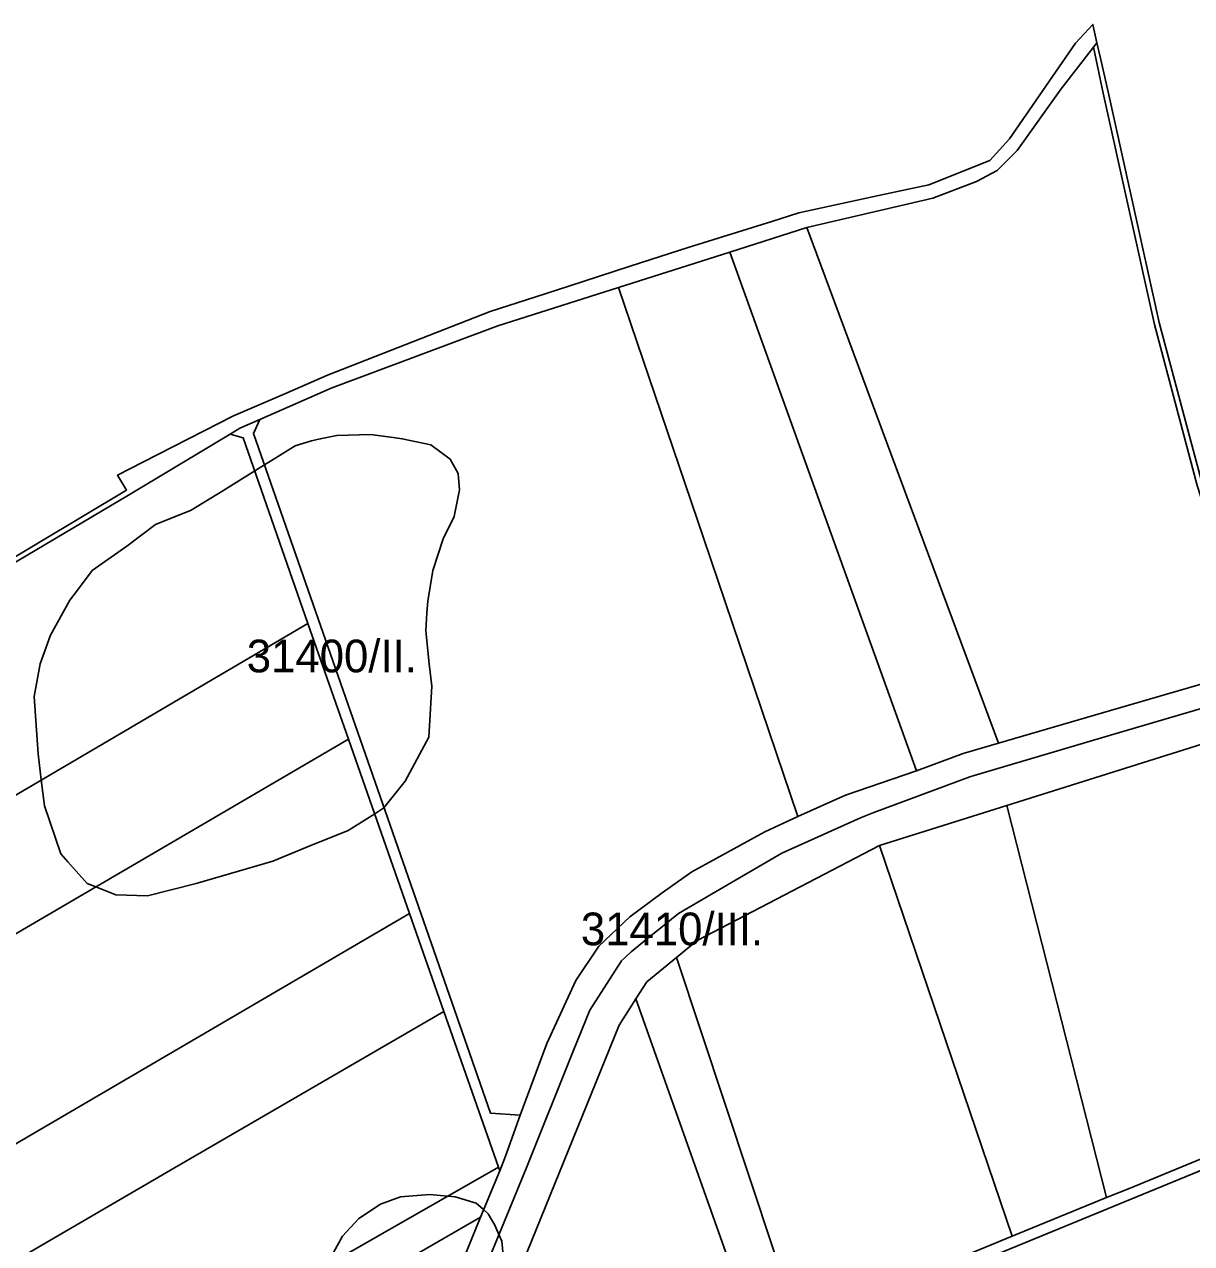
# Model space of a CAD drawing. Extents: x -522079 to -518792, y -1142400 to -1139961.
# Drawn here: x -520538 to -520002, y -1140521 to -1139961 of the extents above; entities that cross this region are included whole.
import ezdxf

# ---------------------------------------------------------------- set-up
doc = ezdxf.new("R2010")
doc.units = 0
for name, color, linetype in [('Hranice parcel', 7, 'Continuous'), ('Parcelní čísla', 7, 'Continuous'), ('Poz předměty', 7, 'Continuous'), ('Značky bodu BP', 7, 'Continuous')]:
    doc.layers.add(name, color=color, linetype=linetype)

msp = doc.modelspace()

# ---------------------------------------------------------------- linework, layer by layer
at = {"layer": 'Hranice parcel'}
for points in [[(-520611.62, -1140247.2), (-520491.09, -1140175.17), (-520495.34, -1140168.3), (-520483.64, -1140162.33), (-520442, -1140141.08), (-520418.53, -1140130.92), (-520398.93, -1140122.43), (-520359.48, -1140107), (-520324.32, -1140093.25), (-520303.34, -1140086.47), (-520288.09, -1140081.53), (-520260.01, -1140072.45), (-520246.26, -1140068.01), (-520233.47, -1140063.87), (-520226.58, -1140061.71), (-520194.98, -1140051.81), (-520182.69, -1140047.96), (-520145.26, -1140039.86), (-520123.02, -1140035.05), (-520094.95, -1140023.82), (-520085.97, -1140013.91), (-520055.62, -1139970.09), (-520047.76, -1139961.42), (-520045.81, -1139969.91), (-520047.4, -1139971.94), (-520062.19, -1139990.92), (-520082.48, -1140019.36), (-520091.68, -1140028.41), (-520101.17, -1140033.45), (-520121.19, -1140041.17), (-520178.95, -1140054.65), (-520214.32, -1140065.91), (-520265.37, -1140082.17), (-520320.72, -1140099.79), (-520397.23, -1140128.42), (-520429.91, -1140142.73), (-520439.13, -1140146.77), (-520443.64, -1140149.48), (-520489.41, -1140176.97), (-520610.57, -1140248.68)], [(-520342.62, -1140543.01), (-520328.73, -1140508.82), (-520319.85, -1140487.51), (-520317.29, -1140480.75), (-520310.52, -1140461.93), (-520298.27, -1140429.16), (-520285.01, -1140400.23), (-520274.33, -1140384.38), (-520260.24, -1140370.94), (-520245.33, -1140359.99), (-520231.71, -1140350.36), (-520198.24, -1140332), (-520183.06, -1140324.86), (-520161.16, -1140315.09), (-520128.63, -1140303.97), (-520107.24, -1140295.95), (-520091.03, -1140291.29), (-520039.59, -1140276.29), (-519972.75, -1140256.9)], [(-519993.22, -1140274.03), (-520037.05, -1140286.83), (-520102.1, -1140306.15), (-520104.17, -1140306.68), (-520148.17, -1140323.1), (-520154.29, -1140325.48), (-520190.37, -1140341.83), (-520222.7, -1140360.61), (-520237.84, -1140369.42), (-520246.72, -1140376.59), (-520251.21, -1140380.2), (-520259.52, -1140387.05), (-520263.92, -1140391.15), (-520278.46, -1140413.78), (-520286.11, -1140432.61), (-520307.77, -1140486.46), (-520327.66, -1140534.75)], [(-519947.24, -1140466.47), (-520104.66, -1140531.14), (-520155.91, -1140552.2), (-520167.57, -1140556.99), (-520262.2, -1140595.87), (-520287.56, -1140604.5), (-520318.61, -1140618.22), (-520330.21, -1140624.54), (-520334.77, -1140627.95), (-520334.5, -1140634.63), (-520342.44, -1140624.55), (-520317.54, -1140611.38), (-520303.27, -1140605.8), (-520289.45, -1140599.87), (-520277.29, -1140595.78), (-520263.96, -1140591.19), (-520201.76, -1140565.63), (-520182.86, -1140557.87), (-520106.55, -1140526.52), (-520084.71, -1140517.54), (-520041.44, -1140499.76), (-520031.39, -1140495.83), (-519949.02, -1140461.79)]]:
    msp.add_lwpolyline(points, dxfattribs=at)
msp.add_lwpolyline([(-520044.21, -1139976.9), (-520040.68, -1139992.3), (-520017.23, -1140098.3), (-519997.42, -1140172.65), (-519970.54, -1140256.24), (-519972.75, -1140256.9), (-519999.86, -1140173.01), (-520019.48, -1140099.15), (-520042.94, -1139993.02), (-520047.4, -1139971.94), (-520045.81, -1139969.91)], close=True, dxfattribs=at)
at = {"layer": 'Parcelní čísla'}
for points in [[(-520178.95, -1140054.65), (-520121.19, -1140041.17), (-520101.17, -1140033.45), (-520091.68, -1140028.41), (-520082.48, -1140019.36), (-520062.19, -1139990.92), (-520047.4, -1139971.94), (-520042.94, -1139993.02), (-520019.48, -1140099.15), (-519999.86, -1140173.01), (-519972.75, -1140256.9), (-520039.59, -1140276.29), (-520091.03, -1140291.29)], [(-520091.03, -1140291.29), (-520107.24, -1140295.95), (-520128.63, -1140303.97), (-520170.5, -1140187.64), (-520214.32, -1140065.91), (-520178.95, -1140054.65)], [(-520265.37, -1140082.17), (-520214.32, -1140065.91), (-520170.5, -1140187.64), (-520128.63, -1140303.97), (-520161.16, -1140315.09), (-520183.06, -1140324.86), (-520226.42, -1140197.01)], [(-520320.72, -1140099.79), (-520265.37, -1140082.17), (-520226.42, -1140197.01), (-520183.06, -1140324.86), (-520198.24, -1140332), (-520231.71, -1140350.36), (-520245.33, -1140359.99), (-520260.24, -1140370.94), (-520274.33, -1140384.38), (-520285.01, -1140400.23), (-520298.27, -1140429.16), (-520310.52, -1140461.93), (-520324.15, -1140461.03), (-520370.19, -1140328.97), (-520432.89, -1140149.1), (-520429.91, -1140142.73), (-520397.23, -1140128.42)], [(-520432.89, -1140149.1), (-520370.19, -1140328.97), (-520324.15, -1140461.03), (-520310.52, -1140461.93), (-520317.29, -1140480.75), (-520319.85, -1140487.51), (-520320.44, -1140485.82), (-520345.47, -1140414.38), (-520361.23, -1140369.4), (-520389.24, -1140289.48), (-520407.86, -1140236.34), (-520437.53, -1140151.12), (-520443.64, -1140149.48), (-520439.13, -1140146.77), (-520429.91, -1140142.73)], [(-520697.54, -1140405.82), (-520704.93, -1140387.92), (-520719.64, -1140344.89), (-520729.96, -1140323.84), (-520727.12, -1140316.09), (-520610.57, -1140248.68), (-520489.41, -1140176.97), (-520443.64, -1140149.48), (-520437.53, -1140151.12), (-520407.86, -1140236.34), (-520563.45, -1140327.62)], [(-520407.86, -1140236.34), (-520389.24, -1140289.48), (-520535.21, -1140374.77), (-520673.87, -1140455.8), (-520683.48, -1140439.85), (-520697.54, -1140405.82), (-520563.45, -1140327.62)], [(-520087.13, -1140319.85), (-519973.33, -1140284.13), (-519917.2, -1140450.72), (-519949.02, -1140461.79), (-520031.39, -1140495.83), (-520041.44, -1140499.76)], [(-520592.52, -1140504.62), (-520608.7, -1140486.32), (-520623.97, -1140478.75), (-520659.41, -1140472.47), (-520666.98, -1140467.24), (-520673.87, -1140455.8), (-520535.21, -1140374.77), (-520389.24, -1140289.48), (-520361.23, -1140369.4)], [(-520041.44, -1140499.76), (-520084.71, -1140517.54), (-520145.65, -1140338.22), (-520087.13, -1140319.85)], [(-520238.71, -1140389.58), (-520229.31, -1140381.82), (-520145.65, -1140338.22), (-520084.71, -1140517.54), (-520106.55, -1140526.52), (-520182.86, -1140557.87)], [(-520361.23, -1140369.4), (-520345.47, -1140414.38), (-520469.06, -1140486.19), (-520562.49, -1140540.48), (-520587.65, -1140510.13), (-520592.52, -1140504.62)], [(-520182.86, -1140557.87), (-520201.76, -1140565.63), (-520257.35, -1140408.66), (-520252.32, -1140400.85), (-520238.71, -1140389.58)], [(-520201.76, -1140565.63), (-520263.96, -1140591.19), (-520277.29, -1140595.78), (-520289.45, -1140599.87), (-520311.64, -1140535.23), (-520265.09, -1140420.72), (-520257.35, -1140408.66)], [(-520345.47, -1140414.38), (-520320.44, -1140485.82), (-520431.13, -1140549.18), (-520503.8, -1140590.78), (-520557.7, -1140546.26), (-520562.49, -1140540.48), (-520469.06, -1140486.19)], [(-519886.24, -1140527.38), (-520082.56, -1140649.64), (-520126.03, -1140587.59), (-520155.91, -1140552.2), (-520104.66, -1140531.14), (-519947.24, -1140466.47), (-519916.36, -1140457.2), (-519904.17, -1140458.14), (-519893.54, -1140491.71)], [(-520490.09, -1140602.11), (-520503.8, -1140590.78), (-520431.13, -1140549.18), (-520320.44, -1140485.82), (-520319.85, -1140487.51), (-520328.73, -1140508.82)], [(-520459.31, -1140627.54), (-520490.09, -1140602.11), (-520328.73, -1140508.82), (-520342.62, -1140543.01), (-520348.21, -1140563.43)]]:
    msp.add_lwpolyline(points, close=True, dxfattribs=at)
at = {"layer": 'Poz předměty'}
for points in [[(-520327.66, -1140534.75), (-520307.77, -1140486.46), (-520286.11, -1140432.61), (-520278.46, -1140413.78), (-520263.92, -1140391.15), (-520259.52, -1140387.05), (-520251.21, -1140380.2), (-520246.72, -1140376.59), (-520237.84, -1140369.42), (-520222.7, -1140360.61), (-520190.37, -1140341.83), (-520154.29, -1140325.48), (-520148.17, -1140323.1), (-520104.17, -1140306.68), (-520102.1, -1140306.15), (-520037.05, -1140286.83), (-519993.22, -1140274.03)], [(-519973.33, -1140284.13), (-520087.13, -1140319.85), (-520145.65, -1140338.22), (-520229.31, -1140381.82), (-520238.71, -1140389.58), (-520252.32, -1140400.85), (-520257.35, -1140408.66), (-520265.09, -1140420.72), (-520311.64, -1140535.23)]]:
    msp.add_lwpolyline(points, dxfattribs=at)
at = {"layer": 'Značky bodu BP'}
for points in [[(-520611.62, -1140247.2), (-520491.09, -1140175.17), (-520495.34, -1140168.3), (-520483.64, -1140162.33), (-520442, -1140141.08), (-520418.53, -1140130.92), (-520398.93, -1140122.43), (-520359.48, -1140107), (-520324.32, -1140093.25), (-520303.34, -1140086.47), (-520288.09, -1140081.53), (-520260.01, -1140072.45), (-520246.26, -1140068.01), (-520233.47, -1140063.87), (-520226.58, -1140061.71), (-520194.98, -1140051.81), (-520182.69, -1140047.96), (-520145.26, -1140039.86), (-520123.02, -1140035.05), (-520094.95, -1140023.82), (-520085.97, -1140013.91), (-520055.62, -1139970.09), (-520047.76, -1139961.42), (-520045.81, -1139969.91), (-520044.21, -1139976.9), (-520040.68, -1139992.3), (-520017.23, -1140098.3), (-519997.42, -1140172.65)], [(-520398.63, -1140529.45), (-520391.98, -1140517.59), (-520384.59, -1140509.44), (-520374.62, -1140502.77), (-520365.38, -1140499.44), (-520352.08, -1140498.33), (-520343.67, -1140499.11), (-520340.26, -1140499.44), (-520330.66, -1140502.4), (-520327.28, -1140505.34), (-520325.12, -1140507.22), (-520322.16, -1140512.41), (-520320.23, -1140516.71), (-520318.84, -1140519.82), (-520318.1, -1140527.97)], [(-520318.1, -1140527.97), (-520318.84, -1140519.82), (-520320.23, -1140516.71), (-520322.16, -1140512.41), (-520325.12, -1140507.22), (-520327.28, -1140505.34), (-520330.66, -1140502.4), (-520340.26, -1140499.44), (-520343.67, -1140499.11), (-520352.08, -1140498.33), (-520365.38, -1140499.44), (-520374.62, -1140502.77), (-520384.59, -1140509.44), (-520391.98, -1140517.59), (-520398.63, -1140529.45)]]:
    msp.add_lwpolyline(points, dxfattribs=at)
for points in [[(-520533.5, -1140269.82), (-520531.63, -1140296.1), (-520530.22, -1140308.12), (-520528.82, -1140320.04), (-520521.34, -1140342.1), (-520518.05, -1140345.78), (-520509.17, -1140355.71), (-520505.24, -1140357.26), (-520496.07, -1140360.87), (-520481.57, -1140361.34), (-520459.11, -1140355.71), (-520424.02, -1140345.38), (-520408.03, -1140338.88), (-520389.4, -1140331.31), (-520377.26, -1140323.65), (-520372.99, -1140320.94), (-520363.2, -1140308.77), (-520352.44, -1140288.6), (-520351.04, -1140265.13), (-520352.18, -1140254.84), (-520353.84, -1140239.78), (-520353.27, -1140231.49), (-520352.91, -1140226.17), (-520350.57, -1140212.09), (-520345.89, -1140197.54), (-520340.74, -1140187.22), (-520338.4, -1140175.02), (-520338.87, -1140167.51), (-520342.61, -1140160.94), (-520351.5, -1140154.36), (-520364.6, -1140151.55), (-520367.65, -1140151.16), (-520370.99, -1140150.73), (-520379.11, -1140149.67), (-520394.55, -1140150.14), (-520402.25, -1140151.69), (-520406.24, -1140152.49), (-520413.73, -1140154.84), (-520427.83, -1140163.6), (-520432.23, -1140166.34), (-520446.95, -1140175.49), (-520461.45, -1140184.41), (-520477.83, -1140190.98), (-520490.93, -1140200.83), (-520506.83, -1140212.09), (-520513.57, -1140221), (-520517.13, -1140225.7), (-520526.02, -1140241.66), (-520530.69, -1140254.8)], [(-520459.11, -1140355.71), (-520481.57, -1140361.34), (-520496.07, -1140360.87), (-520505.24, -1140357.26), (-520509.17, -1140355.71), (-520518.05, -1140345.78), (-520521.34, -1140342.1), (-520528.82, -1140320.04), (-520530.22, -1140308.12), (-520531.63, -1140296.1), (-520533.5, -1140269.82), (-520530.69, -1140254.8), (-520526.02, -1140241.66), (-520517.13, -1140225.7), (-520513.57, -1140221), (-520506.83, -1140212.09), (-520490.93, -1140200.83), (-520477.83, -1140190.98), (-520461.45, -1140184.41), (-520446.95, -1140175.49), (-520432.23, -1140166.34), (-520427.83, -1140163.6), (-520413.73, -1140154.84), (-520406.24, -1140152.49), (-520402.25, -1140151.69), (-520394.55, -1140150.14), (-520379.11, -1140149.67), (-520370.99, -1140150.73), (-520367.65, -1140151.16), (-520364.6, -1140151.55), (-520351.5, -1140154.36), (-520342.61, -1140160.94), (-520338.87, -1140167.51), (-520338.4, -1140175.02), (-520340.74, -1140187.22), (-520345.89, -1140197.54), (-520350.57, -1140212.09), (-520352.91, -1140226.17), (-520353.27, -1140231.49), (-520353.84, -1140239.78), (-520352.18, -1140254.84), (-520351.04, -1140265.13), (-520352.44, -1140288.6), (-520363.2, -1140308.77), (-520372.99, -1140320.94), (-520377.26, -1140323.65), (-520389.4, -1140331.31), (-520408.03, -1140338.88), (-520424.02, -1140345.38)]]:
    msp.add_lwpolyline(points, close=True, dxfattribs=at)

# ---------------------------------------------------------------- texts
for s, rotation, p in [('31400/II.', 360, (-520435.95, -1140258.77)), ('31410/III.', 0, (-520282.64, -1140384.02))]:
    msp.add_text(s, height=15, rotation=rotation, dxfattribs=at).set_placement(p)

doc.saveas('drawing.dxf')
